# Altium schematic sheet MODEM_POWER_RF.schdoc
size 127 x 101 mm
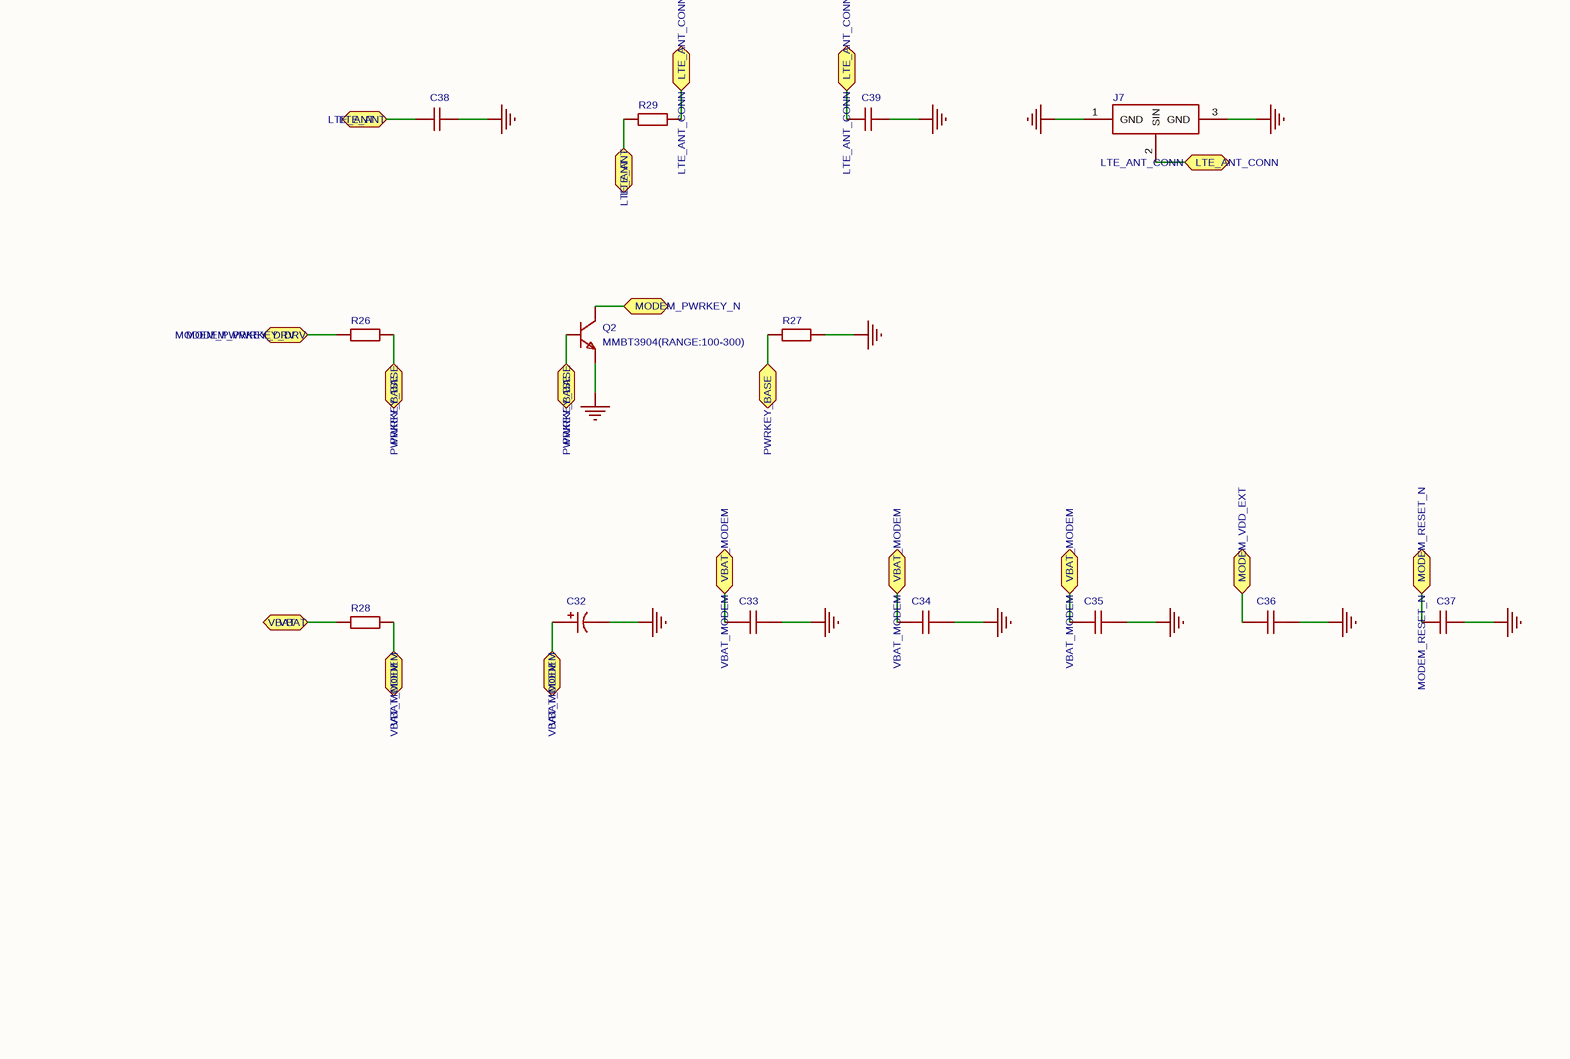
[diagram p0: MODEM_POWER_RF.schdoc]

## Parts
C32  (no value)  [CAP-SMD_BD8.0-L8.3-W8.3-LS9.1-FD_RYRVE6.3V1000UF8X10]
C33  (no value)  [C0805]
C34  (no value)  [C0805]
C35  (no value)  [C0402]
C36  (no value)  [C0402]
C37  (no value)  [C0402]
C38  (no value)  [C0402]
C39  (no value)  [C0402]
J7  (no value)  [RF-SMD_U.FL-R-SMT-1-80]
Q2  MMBT3904(RANGE:100-300)  [SOT-23-3_L2.9-W1.3-P1.90-LS2.4-BR]
R26  (no value)  [R0402]
R27  (no value)  [R0402]
R28  (no value)  [R0402]
R29  (no value)  [R0402]

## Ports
LTE_ANT (bidir), LTE_ANT_CONN (bidir), MODEM_PWRKEY_DRV (bidir), MODEM_PWRKEY_N (bidir), MODEM_RESET_N (bidir), MODEM_VDD_EXT (bidir), PWRKEY_BASE (bidir), VBAT (bidir), VBAT_MODEM (bidir)

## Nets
GND: C32.2 C33.2 C34.2 C35.2 C36.2 C37.2 C38.2 C39.2 J7.1(GND) J7.3(GND) Q2.2(E) R27.2
LTE_ANT: C38.1 R29.1 ; port LTE_ANT
LTE_ANT_CONN: C39.1 J7.2(SIN) R29.2 ; port LTE_ANT_CONN
MODEM_PWRKEY_DRV: R26.1 ; port MODEM_PWRKEY_DRV
MODEM_PWRKEY_N: Q2.3(C) ; port MODEM_PWRKEY_N
MODEM_RESET_N: C37.1 ; port MODEM_RESET_N
MODEM_VDD_EXT: C36.1 ; port MODEM_VDD_EXT
PWRKEY_BASE: Q2.1(B) R26.2 R27.1 ; port PWRKEY_BASE
VBAT: R28.1 ; port VBAT
VBAT_MODEM: C32.1 C33.1 C34.1 C35.1 R28.2 ; port VBAT_MODEM

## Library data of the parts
C32 = RYRVT10V470UF8*10: Manufacturer: HONOR(荣誉); Add into BOM: yes
C33 C34 = CL21A226MAQNNNE: Manufacturer: SAMSUNG(三星); Add into BOM: yes; ModelId: 1ba041120af144c991958decab20d2410819f05c4eef4c71ace90d822a990e87; ModelName: C0805_L2.0-W1.3-H1.3; ModelTransform: 78.74,51.181,0,0,0,0,0,0.0005,0
C35 C36 = CL05B104KO5NNNC: Manufacturer: SAMSUNG(三星); Add into BOM: yes; ModelId: 36a51122f27c49738f86b3bfa98863e00819f05c4eef4c71ace90d822a990e87; ModelName: C0402_L1.0-W0.5-H0.5; ModelTransform: 39.37,19.685,0,0,0,0,0,0,0
C37 = CL05B103KB5NNNC: Manufacturer: SAMSUNG(三星); Add into BOM: yes; ModelId: 36a51122f27c49738f86b3bfa98863e00819f05c4eef4c71ace90d822a990e87; ModelName: C0402_L1.0-W0.5-H0.5; ModelTransform: 39.37,19.685,0,0,0,0,0,0,0
C38 C39 = 0402CG1R0C500NT: DNP — LTE pi shunt tuning placeholder; fit only after VNA tuning; Manufacturer: FH(风华); Add into BOM: no; Convert to PCB: yes; ModelId: 36a51122f27c49738f86b3bfa98863e00819f05c4eef4c71ace90d822a990e87; ModelName: C0402_L1.0-W0.5-H0.5; ModelTransform: 39.37,19.685,0,0,0,0,0,0,0
J7 = U.FL-R-SMT-1(01): Manufacturer: HRS(广濑); Add into BOM: yes; ModelId: 2db29a5880f042f1935df7838af282e70819f05c4eef4c71ace90d822a990e87; ModelTransform: 118.11,118.11,0,180,0,0,0,28.543,0
Q2 = MMBT3904(RANGE:100-300): Manufacturer: CJ(江苏长电/长晶); Add into BOM: yes; ModelId: c62791f0466c4ae2a892c056b845b0ca0819f05c4eef4c71ace90d822a990e87; ModelName: SOT-23-3P_L2.9-W1.3-H1.0-LS2.4-P0.95; ModelTransform: 98.425,114.173,0,180,0,0,0.0005,-0.0005,0
R26 = 0402WGF4701TCE: Manufacturer: UNI-ROYAL(厚声); Add into BOM: yes; ModelId: 98c88bc2b9094f218f3a3e30a70127380819f05c4eef4c71ace90d822a990e87; ModelName: R0402_L1.0-W0.5-H0.4; ModelTransform: 39.37,19.685,0,0,0,0,0,0,0
R27 = 0402WGF4702TCE: Manufacturer: UNI-ROYAL(厚声); Add into BOM: yes; ModelId: 98c88bc2b9094f218f3a3e30a70127380819f05c4eef4c71ace90d822a990e87; ModelName: R0402_L1.0-W0.5-H0.4; ModelTransform: 39.37,19.685,0,0,0,0,0,0,0
R28 R29 = 0402WGF0000TCE: Manufacturer: UNI-ROYAL(厚声); Add into BOM: yes; ModelId: 98c88bc2b9094f218f3a3e30a70127380819f05c4eef4c71ace90d822a990e87; ModelName: R0402_L1.0-W0.5-H0.4; ModelTransform: 39.37,19.685,0,0,0,0,0,0,0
